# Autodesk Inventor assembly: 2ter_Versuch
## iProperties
Created: 2008-03
Part Number: 2ter_Versuch
Document SubType Name: Schweißkonstruktion
Designer: bts
Weld Material: Geschweißter Stahl (weich)
Mass: 237679 g
Surface Area: 43895.4 cm^2
Volume: 30277.6 cm^3
Density: 7.85 g/cm^3
Cost Center: 237,679 kg
Authority: 30277599 mm^3
SaveDate: 2008-03-18
SaveTime: 13:06
TotalMass: 237,679 kg
TotalVolume: 30277599 mm^3
Author: bts
